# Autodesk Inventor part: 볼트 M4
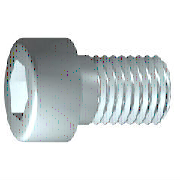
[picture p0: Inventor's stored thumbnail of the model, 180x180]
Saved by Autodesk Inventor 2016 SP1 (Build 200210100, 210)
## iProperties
IsCustomPart: 0
Created: 2012-02
Part Number: 볼트 M4
Material: 스테인리스강
Description: 6각 소켓 머리 캡 나사
Document SubType Name: Modeling
Standard: ISO 4762
Designer: mduedu
Standard Revision: Fourth edition 2004-03-01
Standards Organization: ISO
Language: ko-KR
Size Designation: M4 x 12
Categories: <MemberInstance><Categories><Category DisplayName="조임쇠" InternalName="e4da775c-781d-43d5-af7c-5136215cf5a6" Mnemonic="FSTN"><Category DisplayName="볼트" InternalN
Density: 7.75 g/cm^3
Appearance: 반광택
Author: mduedu
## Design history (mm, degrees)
sketch "스케치1"
  geometry: L1 (-1, 0)-(12, 0); L2 (12, 0)-(12, 2); L3 (12, 2)-(1.75, 2); L4 (1.75, 2)-(1.32, 2); L5 (1.32, 2)-(0, 2); L6 (0, 2)-(0, 3.5); L7 (0, 3.5)-(-4, 3.5); L8 (-4, 3.5)-(-4, 1.732); L9 (-4, 1.732)-(-2, 1.732); L10 (-2, 1.732)-(-1, 0); L11 (-7.2, 0)-(15.2, 0) reference; L12 (0, -0.7)-(0, 4.2) reference; L13 (1.75, 2)-(0, 2)
  constraints: 22 end point, 6 parallel, 2 collinear, 2 perpendicular, 1 horizontal, 1 point on line
  dimensions: "d1" = 10.25 distance from line of L3.end L2 (= GEL); "d2" = 0.42952 distance of L4.end L3.end (computed from GAL); "d3" = 4 distance between parallel lines of L8 L6 (= KOH); "d4" = 2 distance of L8.end L9.end (= INTI); "d5" = 60 deg angle of L10 L1; "d6" = 4 diameter of L3 L1 (= GD); "d7" = 4 diameter of L5 L1 (= BDM); "d8" = 3.4641 diameter of L9 L1 (= 1.1547 x SW); "d9" = 7 diameter of L7 L1 (= KOD); "d26" = 12 distance between parallel lines of L12 L2 (= NLG)
revolve "본체" sketch "스케치1" stored, may be unused: angle "d10" = 90 deg
sketch "스케치2"
  geometry: L1 (0, -4.9)-(0, 4.9) reference; L2 (-4.9, 0)-(4.9, 0) reference; L3 (1.732, 0)-(0.866, -1.5); L4 (0.866, -1.5)-(-0.866, -1.5); L5 (-0.866, -1.5)-(-1.732, 0); L6 (-1.732, 0)-(-0.866, 1.5); L7 (-0.866, 1.5)-(0.866, 1.5); L8 (0.866, 1.5)-(1.732, 0); 2 further points
  constraints: 12 end point, 1 coincident, 1 horizontal alignment, 1 point on line, 12 other
extrude "슬롯" join sketch "스케치2" stored distance "d11" = 10; taper "d12" = 0 deg
workplane "Work Plane1"
fillet "Fillet2" dims "d30" = 0.1 (= R)
body "Solid1"
fillet "모깎기1" dims "d17" = 0.4 (= RR)
feature "스레드" dims "d13" = 10.25 (= GEL), "d14" = 0
chamfer "모따기1" distance "d15" = 0.42941 (= -0.5 x SPD + 0.5 x GD); stored, may be unused: second distance "d16" = 0.42941 (= GUL), angle "d27" = 45 deg
other parameters: "GD" = 4 [user parameter; used in 2 equation terms], "NLG" = 12 [user parameter; used in 1 equation term], "GEL" = 10.25 [user parameter; used in 2 equation terms], "KOD" = 7 [user parameter; used in 1 equation term], "KOH" = 4 [user parameter; used in 1 equation term], "INTI" = 2 [user parameter; used in 1 equation term], "GAL" = 0.42941 (= 0.61345 x PTC) [user parameter; used in 1 equation term], "GUL" = 0.42941 (= 0.61345 x PTC) [user parameter; used in 1 equation term], "BDM" = 4 (= NND) [user parameter; used in 1 equation term], "SW" = 3 [user parameter; used in 2 equation terms], "RR" = 0.4 [user parameter; used in 1 equation term], "SPD" = 3.14117 (= NND - 1.2269 x PTC) [user parameter; used in 1 equation term], "d19" = 0, "d28" = 0, "d29" = 0, "R" = 0.1 [user parameter; used in 1 equation term], "TOA" = 30 deg [user parameter], "GD1" = 3.14117 (= THREADDIA - 1.2269 x PTC) [user parameter], "THREADDIA" = 4 [user parameter; used in 1 equation term], "FAWI" = 45 deg [user parameter], "TPU" = 14.28571 (computed from PTC) [user parameter], "PTC" = 0.7 [user parameter; used in 5 equation terms], "NND" = 4 [user parameter; used in 2 equation terms], "E0" = 3.465 (= 1.155 x SW) [user parameter]
